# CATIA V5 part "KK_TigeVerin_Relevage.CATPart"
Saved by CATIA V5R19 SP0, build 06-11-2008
Part number: Tige verin de relevage
Bounding box of the stored display mesh (mm): x -321.132 to -209.003, y -58 to 58, z -1320.544 to -319.296
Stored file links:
  G:\Khaled_CFAO_2011\ST2M\ST2M_GR2\aboulegue\Khaled\CAD_thinkMOTION\KK_TigeVerin_Relevage.CATPart
  G:\Khaled_CFAO_2011\ST2M\ST2M_GR2\aboulegue\Khaled\CAD_thinkMOTION\KK_Train_Atterrissage.CATProduct
  G:\Khaled_CFAO_2011\ST2M\ST2M_GR2\aboulegue\Khaled\CAD_thinkMOTION\KK_SqueletteTige_VerinRelevage.CATPart
  G:\Khaled_CFAO_2011\ST2M\ST2M_GR2\aboulegue\Khaled\CAD_thinkMOTION\KK_SquelettePanneau_Pivotant.CATPart
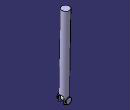
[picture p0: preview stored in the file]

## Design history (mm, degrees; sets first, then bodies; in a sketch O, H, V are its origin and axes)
Set1
  Plane1 "Plan de reference corps de verin de relevage": linked copy from another document
  Line1: linked copy from another document
  Point1 "Point.21": linked copy from another document
  Line2: linked copy from another document
  Plane2 "Plan panneau pivotant1": linked copy from another document
  Point2 "Point.10": linked copy from another document
Body1 (main body)
  Sketch1 on Plane1, origin (-278.7682, 0, -4.978), H (0, -1, 0), V (-0.0179, 0, 0.9998)
    point P1 (0, -315.2253)
    line L1 (0, -315.2253) -> (48, -315.2253)
    line L2 (48, -315.2253) -> (48, -1315.2253)
    line L3 (48, -1315.2253) -> (0, -1315.2253)
    line L4 (0, -1315.2253) -> (0, -315.2253)
    reference projected line E1 (0, -1275.2253) -> (0, -315.2253) from Line1
    reference projected point E2 (0, -315.2253) from Point1
    reference projected line E3 (200, -1275.2253) -> (-200, -1275.2253) from Line2
    distance E3 L3 = 40
    length L3 = 48
    horizontal: L1 H, L3 H
    vertical: L2 V, L4 V
    coincidence: E1 L4, E2 P1
  Shaft1: profile Sketch1, axis Line1, angle 360
  Sketch2 on Plane1, origin (-278.7682, 0, -4.978), H (0, -1, 0), V (-0.0179, 0, 0.9998)
  Sketch3 on Plane1, origin (-278.7682, 0, -4.978), H (0, -1, 0), V (-0.0179, 0, 0.9998)
    line L1 (-25, -1225.2253) -> (25, -1225.2253)
    line L2 (25, -1225.2253) -> (25, -1325.2253)
    line L3 (25, -1325.2253) -> (-25, -1325.2253)
    line L4 (-25, -1325.2253) -> (-25, -1225.2253)
    reference projected line E1 (0, -1275.2253) -> (0, -315.2253) from Line1
    reference projected line E2 (200, -1275.2253) -> (-200, -1275.2253) from Line2
    length L3 = 50
    distance E1 L2 = 25
    distance E2 L1 = 50
    length L2 = 100
    horizontal: L1 H, L3 H
    vertical: L2 V, L4 V
  Pocket1: profile Sketch3, direction (0.9998, 0, 0.0179), length 50, mirrored extent
  Fillet1: radius 24, on edge [face of Pocket1 from Sketch3.L4 | face of Pocket1 from Sketch3.L1]; edge [face of Pocket1 from Sketch3.L1 | face of Pocket1 from Sketch3.L2]
  Fillet2: radius 5, on edge [face of Pocket1 from Sketch3.L4 | face of Shaft1 from Sketch1.L2]; edge [face of Fillet1 | face of Shaft1 from Sketch1.L2] (x4); edge [face of Shaft1 from Sketch1.L2 | face of Pocket1 from Sketch3.L2]; face of Shaft1 from Sketch1.L3 (x2); edge [face of Shaft1 from Sketch1.L2 | face of Pocket1 from Sketch3.L4]; edge [face of Pocket1 from Sketch3.L2 | face of Shaft1 from Sketch1.L2]
  Sketch4 on Plane2, origin (0, 0, 0), H (1, 0, 0), V (0, 0, 1)
    circle A1 centre (-256, -1280) radius 24
    point P1 (-256, -1280)
    reference projected point E1 (-256, -1280) from Point2
    radius A1 = 24
    coincidence: E1 P1
  Pocket2: profile Sketch4, direction (0, 1, 0), length 50, mirrored extent
  Sketch5 on Plane1, origin (-278.7682, 0, -4.978), H (0, -1, 0), V (-0.0179, 0, 0.9998)
    line L1 (-58, -1251.2253) -> (48, -1251.2253)
    line L2 (48, -1251.2253) -> (48, -1241.2253)
    line L3 (48, -1241.2253) -> (58, -1241.2253)
    line L4 (58, -1241.2253) -> (58, -1275.2253)
    line L5 (58, -1275.2253) -> (-58, -1275.2253)
    line L6 (-58, -1275.2253) -> (-58, -1251.2253)
    reference projected line E1 (200, -1275.2253) -> (-200, -1275.2253) from Line2
    reference projected line E2 (0, -1275.2253) -> (0, -315.2253) from Line1
    length L5 = 116
    length L4 = 34
    length L6 = 24
    distance L4 E2 = 58
    length L3 = 10
    horizontal: L1 H, L3 H, L5 H
    vertical: L2 V, L4 V, L6 V
    coincidence: L5 E1
  Shaft2: profile Sketch5, axis Line2, angle 360
  Sketch6 on Plane1, origin (-278.7682, 0, -4.978), H (0, -1, 0), V (-0.0179, 0, 0.9998)
    line L1 (-58, -1241.2253) -> (-48, -1241.2253)
    line L2 (-48, -1241.2253) -> (-48, -1251.2253)
    line L3 (-48, -1251.2253) -> (-58, -1251.2253)
    line L4 (-58, -1251.2253) -> (-58, -1241.2253)
    reference projected line E1 (200, -1275.2253) -> (-200, -1275.2253) from Line2
    reference projected line E2 (0, -1275.2253) -> (0, -315.2253) from Line1
    distance L3 E1 = 24
    length L2 = 10
    length L3 = 10
    distance E2 L2 = 48
    horizontal: L1 H, L3 H
    vertical: L2 V, L4 V
  Shaft3: profile Sketch6, axis Line2, angle 360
